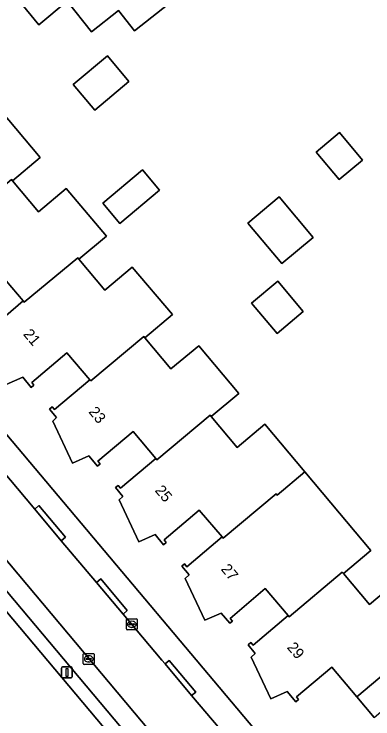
# Model space of a CAD drawing. Extents: x 157320 to 158835, y 386650 to 388491.
# Drawn here: x 157743.6 to 157776.4, y 387347.6 to 387412.1 of the extents above; entities that cross this region are included whole.
import ezdxf

# ---------------------------------------------------------------- set-up
doc = ezdxf.new("R2010")
doc.units = 0
for name, color, linetype in [('IMGEO_Erf', 7, 'Continuous'), ('IMGEO_Groenvoorziening', 7, 'Continuous'), ('IMGEO_Kolk', 7, 'Continuous'), ('IMGEO_Lichtmast', 7, 'Continuous'), ('IMGEO_Pand', 7, 'Continuous'), ('IMGEO_Pand_nummerreeks', 7, 'Continuous'), ('IMGEO_Parkeervlak_open', 7, 'Continuous'), ('IMGEO_Rijbaan_lokaal_open', 7, 'Continuous'), ('IMGEO_Voetpad_open', 7, 'Continuous')]:
    doc.layers.add(name, color=color, linetype=linetype)

msp = doc.modelspace()

# ---------------------------------------------------------------- linework, layer by layer
at = {"layer": 'IMGEO_Erf'}
for points in [[(157759.233, 387414.262), (157754.614, 387410.596), (157753.155, 387412.465), (157750.68, 387410.512), (157748.464, 387413.316), (157745.87, 387411.159), (157744.023, 387413.382)], [(157742.316, 387403.352), (157745.997, 387398.995), (157743.466, 387396.871), (157745.847, 387394.033), (157748.378, 387396.157), (157752.054, 387391.801), (157749.526, 387389.702), (157751.886, 387386.86), (157754.414, 387388.959), (157758.104, 387384.612), (157755.57, 387382.487), (157757.953, 387379.646), (157760.487, 387381.771), (157764.151, 387377.406), (157761.636, 387375.292), (157764.012, 387372.465), (157766.535, 387374.585), (157770.191, 387370.217), (157772.585, 387367.394), (157776.248, 387363.03), (157773.722, 387360.91), (157776.1, 387358.077), (157778.626, 387360.198)], [(157718.465, 387402.672), (157769.321, 387342.243)], [(157741.235, 387383.142), (157744.435, 387385.869), (157742.349, 387388.316)], [(157776.545, 387347.744), (157774.955, 387349.632), (157772.667, 387352.35), (157769.42, 387349.617), (157769.626, 387349.372), (157769.381, 387349.166), (157768.595, 387350.126), (157767.095, 387349.449), (157765.293, 387353.27), (157765.656, 387353.594), (157765.005, 387354.398), (157765.247, 387354.603), (157765.458, 387354.354), (157768.66, 387357.075), (157766.575, 387359.529), (157763.365, 387356.802), (157763.571, 387356.56), (157763.329, 387356.355), (157762.536, 387357.297), (157761.046, 387356.639), (157759.255, 387360.469), (157759.607, 387360.781), (157758.948, 387361.582), (157759.191, 387361.787), (157759.402, 387361.537), (157762.626, 387364.26), (157760.543, 387366.725), (157757.32, 387364.002), (157757.525, 387363.759), (157757.282, 387363.554), (157756.509, 387364.49), (157755.002, 387363.824), (157753.208, 387367.646), (157753.562, 387367.976), (157752.891, 387368.78), (157753.134, 387368.984), (157753.345, 387368.734), (157756.565, 387371.443), (157754.488, 387373.911), (157751.261, 387371.195), (157751.465, 387370.952), (157751.222, 387370.748), (157750.438, 387371.682), (157748.933, 387371.021), (157747.147, 387374.858), (157747.483, 387375.198), (157746.837, 387375.973), (157747.08, 387376.178), (157747.292, 387375.927), (157750.524, 387378.654), (157748.439, 387381.125), (157745.207, 387378.399), (157745.412, 387378.155), (157745.169, 387377.95), (157744.387, 387378.875), (157742.879, 387378.229)]]:
    msp.add_lwpolyline(points, dxfattribs=at)
for points in [[(157752.139, 387408.306), (157754.105, 387405.968), (157750.983, 387403.342), (157749.016, 387405.679)], [(157775.477, 387398.771), (157773.343, 387396.981), (157771.241, 387399.488), (157773.375, 387401.277)], [(157756.91, 387396.012), (157753.276, 387392.945), (157751.703, 387394.809), (157755.337, 387397.876)], [(157770.953, 387391.686), (157768.097, 387389.291), (157764.99, 387392.995), (157767.847, 387395.39)], [(157767.723, 387387.669), (157770.048, 387384.911), (157767.656, 387382.895), (157765.331, 387385.653)]]:
    msp.add_lwpolyline(points, close=True, dxfattribs=at)
at = {"layer": 'IMGEO_Groenvoorziening'}
msp.add_lwpolyline([(157758.699, 387338.613), (157708.688, 387398.154)], dxfattribs=at)
at = {"layer": 'IMGEO_Kolk'}
for p, q in [((157753.944, 387356.765), (157754.796, 387356.765)), ((157753.869, 387355.839), (157753.869, 387356.691)), ((157754.128, 387356.259), (157754.128, 387356.271)), ((157754.566, 387356.222), (157754.168, 387356.222)), ((157754.171, 387356.308), (157754.569, 387356.308)), ((157754.357, 387356.545), (157754.382, 387356.545)), ((157754.612, 387356.271), (157754.612, 387356.259)), ((157754.87, 387356.691), (157754.87, 387355.839)), ((157754.796, 387355.765), (157753.944, 387355.765)), ((157754.38, 387355.985), (157754.355, 387355.985)), ((157749.93, 387352.671), (157749.93, 387353.523)), ((157750.005, 387353.597), (157750.857, 387353.597)), ((157750.931, 387353.523), (157750.931, 387352.671)), ((157750.189, 387353.091), (157750.189, 387353.103)), ((157750.627, 387353.054), (157750.229, 387353.054)), ((157750.232, 387353.14), (157750.63, 387353.14)), ((157750.418, 387353.377), (157750.443, 387353.377)), ((157750.673, 387353.103), (157750.673, 387353.091)), ((157750.857, 387352.597), (157750.005, 387352.597)), ((157750.441, 387352.817), (157750.416, 387352.817))]:
    msp.add_line(p, q, dxfattribs=at)
for points in [[(157753.944, 387356.765), (157754.796, 387356.765)], [(157753.869, 387355.839), (157753.869, 387356.691)], [(157754.87, 387356.691), (157754.87, 387355.839)], [(157754.796, 387355.765), (157753.944, 387355.765)], [(157749.93, 387352.671), (157749.93, 387353.523)], [(157750.005, 387353.597), (157750.857, 387353.597)], [(157750.931, 387353.523), (157750.931, 387352.671)], [(157750.857, 387352.597), (157750.005, 387352.597)]]:
    msp.add_lwpolyline(points, dxfattribs=at)
for centre, radius, start, end in [((157753.946, 387356.689), 0.0765, 91.55205, 178.44795), ((157753.946, 387356.689), 0.0765, 91.55205, 178.44795), ((157754.794, 387356.689), 0.0765, 1.55205, 88.44795), ((157754.794, 387356.689), 0.0765, 1.55205, 88.44795), ((157754.168, 387356.268), 0.0403, 85.87752, 175.75265), ((157754.165, 387356.258), 0.0366, 178.93798, 274.71019), ((157754.569, 387356.265), 0.043, 264.86636, 352.45326), ((157754.573, 387356.27), 0.0386, 1.73085, 96.63898), ((157753.946, 387355.841), 0.0765, 181.55205, 268.44795), ((157753.946, 387355.841), 0.0765, 181.55205, 268.44795), ((157754.794, 387355.841), 0.0765, 271.55205, 358.44795), ((157754.794, 387355.841), 0.0765, 271.55205, 358.44795), ((157750.007, 387353.521), 0.0765, 91.55205, 178.44795), ((157750.007, 387353.521), 0.0765, 91.55205, 178.44795), ((157750.855, 387353.521), 0.0765, 1.55205, 88.44795), ((157750.855, 387353.521), 0.0765, 1.55205, 88.44795), ((157750.229, 387353.1), 0.0403, 85.87752, 175.75265), ((157750.226, 387353.09), 0.0366, 178.93798, 274.71019), ((157750.63, 387353.097), 0.043, 264.86636, 352.45326), ((157750.634, 387353.102), 0.0386, 1.73085, 96.63898), ((157750.007, 387352.673), 0.0765, 181.55205, 268.44795), ((157750.007, 387352.673), 0.0765, 181.55205, 268.44795), ((157750.855, 387352.673), 0.0765, 271.55205, 358.44795), ((157750.855, 387352.673), 0.0765, 271.55205, 358.44795)]:
    msp.add_arc(centre, radius, start, end, dxfattribs=at)
for centre, major_axis, ratio, start_param, end_param in [((157754.356, 387356.265), (-0.387, 0.002), 0.722429, 4.712389, 7.853982), ((157754.381, 387356.265), (-0.39, 0.002), 0.717154, 1.570796, 4.712389), ((157750.417, 387353.097), (-0.387, 0.002), 0.722429, 4.712389, 7.853982), ((157750.442, 387353.097), (-0.39, 0.002), 0.717154, 1.570796, 4.712389)]:
    msp.add_ellipse(centre, major_axis=major_axis, ratio=ratio, start_param=start_param, end_param=end_param, dxfattribs=at)
at = {"layer": 'IMGEO_Lichtmast'}
for p, q in [((157747.933, 387351.458), (157747.933, 387352.258)), ((157747.933, 387352.258), (157747.933, 387351.458)), ((157748.033, 387352.358), (157748.823, 387352.358)), ((157748.823, 387352.358), (157748.033, 387352.358)), ((157748.923, 387352.258), (157748.923, 387351.458)), ((157748.923, 387351.458), (157748.923, 387352.258)), ((157748.823, 387351.358), (157748.033, 387351.358)), ((157748.033, 387351.358), (157748.823, 387351.358))]:
    msp.add_line(p, q, dxfattribs=at)
msp.add_lwpolyline([(157748.353, 387352.233), (157748.503, 387352.233), (157748.503, 387351.483), (157748.353, 387351.483), (157748.353, 387352.233)], dxfattribs=at)
for centre, start, end in [((157748.033, 387352.258), 90, 180), ((157748.033, 387352.258), 90, 180), ((157748.823, 387352.258), 0, 90), ((157748.823, 387352.258), 360, 90), ((157748.033, 387351.458), 180, 270), ((157748.033, 387351.458), 180, 270), ((157748.823, 387351.458), 270, 0), ((157748.823, 387351.458), 270, 0)]:
    msp.add_arc(centre, 0.1, start, end, dxfattribs=at)
at = {"layer": 'IMGEO_Pand'}
for points in [[(157759.233, 387414.262), (157750.673, 387425.09), (157750.226, 387424.737), (157749.92, 387425.105), (157746.045, 387423.432), (157746.68, 387421.925), (157745.716, 387421.168), (157745.915, 387420.917), (157746.174, 387421.122), (157747.946, 387418.88), (157748.811, 387417.785), (157746.473, 387415.937), (157748.464, 387413.316), (157750.68, 387410.512), (157753.155, 387412.465), (157754.614, 387410.596)], [(157748.464, 387413.316), (157746.473, 387415.937), (157745.057, 387417.64), (157743.532, 387419.475), (157740.827, 387417.227), (157744.023, 387413.382), (157745.87, 387411.159)], [(157752.139, 387408.306), (157749.016, 387405.679), (157750.983, 387403.342), (157754.105, 387405.968)], [(157738.418, 387393.014), (157738.514, 387392.899), (157743.37, 387396.986), (157743.466, 387396.871), (157745.997, 387398.995), (157742.316, 387403.352), (157739.775, 387401.226), (157737.398, 387404.067), (157737.302, 387404.182), (157732.489, 387400.12), (157732.393, 387400.235), (157729.139, 387397.508), (157728.927, 387397.76), (157728.682, 387397.555), (157729.355, 387396.747), (157728.982, 387396.452), (157730.779, 387392.605), (157732.276, 387393.259), (157733.08, 387392.342), (157733.324, 387392.546), (157733.12, 387392.789), (157736.348, 387395.489)], [(157775.477, 387398.771), (157773.375, 387401.277), (157771.241, 387399.488), (157773.343, 387396.981)], [(157756.91, 387396.012), (157755.337, 387397.876), (157751.703, 387394.809), (157753.276, 387392.945)], [(157738.418, 387393.014), (157735.189, 387390.315), (157734.979, 387390.566), (157734.735, 387390.362), (157735.391, 387389.578), (157735.023, 387389.27), (157736.834, 387385.414), (157738.333, 387386.068), (157739.12, 387385.135), (157739.361, 387385.34), (157739.149, 387385.589), (157742.349, 387388.316), (157744.435, 387385.869), (157744.532, 387385.755), (157749.43, 387389.817), (157749.526, 387389.702), (157752.054, 387391.801), (157748.378, 387396.157), (157745.847, 387394.033), (157743.466, 387396.871), (157743.37, 387396.986), (157738.514, 387392.899)], [(157768.097, 387389.291), (157770.953, 387391.686), (157767.847, 387395.39), (157764.99, 387392.995)], [(157749.526, 387389.702), (157749.43, 387389.817), (157744.532, 387385.755), (157744.435, 387385.869), (157741.235, 387383.142), (157741.023, 387383.39), (157740.782, 387383.185), (157741.431, 387382.395), (157741.083, 387382.064), (157742.879, 387378.229), (157744.387, 387378.875), (157745.169, 387377.95), (157745.412, 387378.155), (157745.207, 387378.399), (157748.439, 387381.125), (157750.524, 387378.654), (157750.621, 387378.539), (157755.474, 387382.602), (157755.57, 387382.487), (157758.104, 387384.612), (157754.414, 387388.959), (157751.886, 387386.86)], [(157767.723, 387387.669), (157765.331, 387385.653), (157767.656, 387382.895), (157770.048, 387384.911)], [(157755.57, 387382.487), (157755.474, 387382.602), (157750.621, 387378.539), (157750.524, 387378.654), (157747.292, 387375.927), (157747.08, 387376.178), (157746.837, 387375.973), (157747.483, 387375.198), (157747.147, 387374.858), (157748.933, 387371.021), (157750.438, 387371.682), (157751.222, 387370.748), (157751.465, 387370.952), (157751.261, 387371.195), (157754.488, 387373.911), (157756.565, 387371.443), (157756.662, 387371.328), (157761.539, 387375.407), (157761.636, 387375.292), (157764.151, 387377.406), (157760.487, 387381.771), (157757.953, 387379.646)], [(157762.626, 387364.26), (157762.723, 387364.145), (157767.582, 387368.215), (157767.679, 387368.1), (157770.191, 387370.217), (157766.535, 387374.585), (157764.012, 387372.465), (157761.636, 387375.292), (157761.539, 387375.407), (157756.662, 387371.328), (157756.565, 387371.443), (157753.345, 387368.734), (157753.134, 387368.984), (157752.891, 387368.78), (157753.562, 387367.976), (157753.208, 387367.646), (157755.002, 387363.824), (157756.509, 387364.49), (157757.282, 387363.554), (157757.525, 387363.759), (157757.32, 387364.002), (157760.543, 387366.725)], [(157776.248, 387363.03), (157772.585, 387367.394), (157770.191, 387370.217), (157767.679, 387368.1), (157767.582, 387368.215), (157762.723, 387364.145), (157762.626, 387364.26), (157759.402, 387361.537), (157759.191, 387361.787), (157758.948, 387361.582), (157759.607, 387360.781), (157759.255, 387360.469), (157761.046, 387356.639), (157762.536, 387357.297), (157763.329, 387356.355), (157763.571, 387356.56), (157763.365, 387356.802), (157766.575, 387359.529), (157768.66, 387357.075), (157768.757, 387356.961), (157773.626, 387361.025), (157773.722, 387360.91)], [(157782.289, 387355.834), (157779.075, 387359.664), (157778.626, 387360.198), (157776.1, 387358.077), (157773.722, 387360.91), (157773.626, 387361.025), (157768.757, 387356.961), (157768.66, 387357.075), (157765.458, 387354.354), (157765.247, 387354.603), (157765.005, 387354.398), (157765.656, 387353.594), (157765.293, 387353.27), (157767.095, 387349.449), (157768.595, 387350.126), (157769.381, 387349.166), (157769.626, 387349.372), (157769.42, 387349.617), (157772.667, 387352.35), (157774.955, 387349.632), (157777.634, 387351.897)], [(157777.634, 387351.897), (157774.955, 387349.632), (157776.545, 387347.744), (157779.224, 387350.009)]]:
    msp.add_lwpolyline(points, close=True, dxfattribs=at)
at = {"layer": 'IMGEO_Parkeervlak_open'}
for points in [[(157762.889, 387338.291), (157715.974, 387394.208)], [(157716.57, 387390.664), (157759.803, 387339.178)]]:
    msp.add_lwpolyline(points, dxfattribs=at)
at = {"layer": 'IMGEO_Rijbaan_lokaal_open'}
msp.add_lwpolyline([(157720.689, 387396.303), (157720.048, 387397.053), (157717.207, 387400.424), (157713.38, 387397.308), (157715.974, 387394.208), (157762.889, 387338.291), (157763.878, 387337.111), (157767.71, 387340.371), (157766.782, 387341.508), (157764.366, 387344.391), (157759.838, 387349.746), (157757.416, 387352.641), (157757.119, 387352.995), (157753.572, 387357.197), (157751.143, 387360.104), (157747.911, 387363.919), (157745.484, 387366.812), (157741.669, 387371.361), (157739.241, 387374.249), (157735.374, 387378.841), (157732.962, 387381.742), (157729.435, 387385.897), (157727.014, 387388.783), (157723.133, 387393.384)], close=True, dxfattribs=at)
at = {"layer": 'IMGEO_Voetpad_open'}
for points in [[(157773.051, 387338.018), (157769.321, 387342.243), (157718.465, 387402.672)], [(157708.688, 387398.154), (157758.699, 387338.613)], [(157759.803, 387339.178), (157716.57, 387390.664)], [(157741.669, 387371.361), (157745.484, 387366.812), (157745.867, 387367.133), (157748.294, 387364.24), (157747.911, 387363.919), (157751.143, 387360.104), (157751.526, 387360.424), (157753.955, 387357.517), (157753.572, 387357.197), (157757.119, 387352.995), (157757.416, 387352.641), (157757.799, 387352.961), (157760.221, 387350.066), (157759.838, 387349.746), (157764.366, 387344.391)]]:
    msp.add_lwpolyline(points, dxfattribs=at)
for points in [[(157745.484, 387366.812), (157747.911, 387363.919), (157748.294, 387364.24), (157745.867, 387367.133)], [(157753.572, 387357.197), (157753.955, 387357.517), (157751.526, 387360.424), (157751.143, 387360.104)], [(157759.838, 387349.746), (157760.221, 387350.066), (157757.799, 387352.961), (157757.416, 387352.641)]]:
    msp.add_lwpolyline(points, close=True, dxfattribs=at)

# ---------------------------------------------------------------- texts
at = {"layer": 'IMGEO_Pand_nummerreeks'}
for s, rotation, p in [('21', 310.02089, (157744.38, 387382.802)), ('23', 310.04381, (157750.359, 387375.693)), ('25', 310.20997, (157756.426, 387368.492)), ('27', 310.05527, (157762.469, 387361.293)), ('29', 310.27872, (157768.514, 387354.119))]:
    msp.add_text(s, height=1, rotation=rotation, dxfattribs=at).set_placement(p)

doc.saveas('drawing.dxf')
